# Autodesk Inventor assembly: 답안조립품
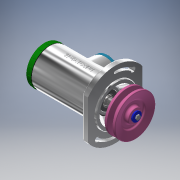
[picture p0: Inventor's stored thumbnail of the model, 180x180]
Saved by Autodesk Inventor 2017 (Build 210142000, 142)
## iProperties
Part Number: 답안조립품
Material: 일반
Document SubType Name: Assembly
Designer: MRC
Author: MRC
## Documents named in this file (21)
- C:\Users\MRC\Desktop\720506V1006\답안조립품.iam
- C:\Users\MRC\Desktop\720506V1006\축.ipt
- C:\Users\MRC\Desktop\720506V1006\베어링 6202.ipt
- C:\Users\MRC\Desktop\720506V1006\부시1.ipt
- C:\Users\MRC\Desktop\720506V1006\멈춤링 35 x 1.6.ipt
- C:\Users\MRC\Desktop\720506V1006\멈춤링 15 x 1.ipt
- C:\Users\MRC\Desktop\720506V1006\부시2.ipt
- C:\Users\MRC\Desktop\720506V1006\와셔 10 x 21.ipt
- C:\Users\MRC\Desktop\720506V1006\너트 M10.ipt
- C:\Users\MRC\Desktop\720506V1006\본체.ipt
- C:\Users\MRC\Desktop\720506V1006\개스킷.ipt
- C:\Users\MRC\Desktop\720506V1006\사이드 커버.ipt
- 사이드 커버.ipt
- C:\Users\MRC\Desktop\720506V1006\탑 커버.ipt
- C:\Users\MRC\Desktop\720506V1006\와셔 3 x 6.ipt
- C:\Users\MRC\Desktop\720506V1006\십자볼트 M3 x 10.ipt
- C:\Users\MRC\Desktop\720506V1006\오일 실 15 x 30 x 7.ipt
- C:\Users\MRC\Desktop\720506V1006\키 4 x 4.ipt
- C:\Users\MRC\Desktop\720506V1006\V-벨트풀리.ipt
- C:\Users\MRC\Desktop\720506V1006\와셔 4 x 16.ipt
- C:\Users\MRC\Desktop\720506V1006\볼트 M4 x 10.ipt
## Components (3 placed, 3 different names)
1. 개스킷:1
2. V-벨트풀리:1 — 플러쉬:3
3. ISO 4017 M4 x 10:1
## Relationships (1: Flush 1)
- 플러쉬:3 [Flush]: V-벨트풀리:1
